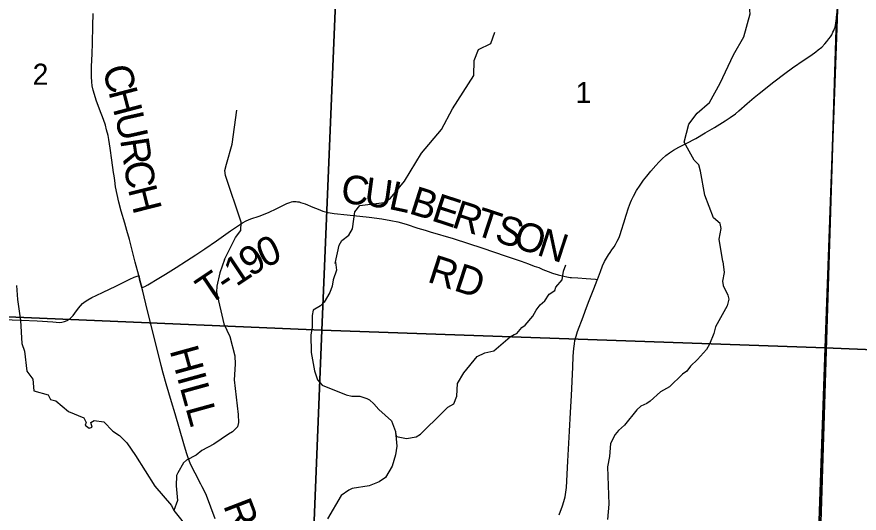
# Model space of a CAD drawing. Extents: x 0 to 34, y 0 to 22.
# Drawn here: x 4.017 to 5.686, y 19.003 to 19.987 of the extents above; entities that cross this region are included whole.
import ezdxf

# ---------------------------------------------------------------- set-up
doc = ezdxf.new("R2010")
doc.units = 0
for name, color, linetype in [('GM_X_County_Road', 7, 'Continuous'), ('GM_X_County_Road_Text', 7, 'Continuous'), ('GM_X_Minor_River', 7, 'Continuous'), ('GM_X_Rail_Line', 7, 'Continuous'), ('GM_X_Section', 7, 'Continuous'), ('GM_X_Section_Text', 7, 'Continuous'), ('GM_X_State_Route', 7, 'Continuous'), ('GM_X_Township_Road', 7, 'Continuous'), ('GM_X_Township_Road_Text', 7, 'Continuous')]:
    doc.layers.add(name, color=color, linetype=linetype)

msp = doc.modelspace()

# ---------------------------------------------------------------- linework, layer by layer
at = {"layer": 'GM_X_County_Road'}
for points in [[(4.2581, 19.4742), (4.2513, 19.5005), (4.2443, 19.5275), (4.2398, 19.5455), (4.2349, 19.5635), (4.2305, 19.5783), (4.2234, 19.602), (4.2186, 19.62), (4.2152, 19.635), (4.2124, 19.6502), (4.2106, 19.6625), (4.2094, 19.6717), (4.2084, 19.6788), (4.205, 19.703), (4.2015, 19.7267), (4.1987, 19.7437), (4.1973, 19.7518), (4.1946, 19.7631), (4.1921, 19.7723), (4.1881, 19.7839), (4.1806, 19.8042), (4.1741, 19.8217), (4.1707, 19.8329), (4.1682, 19.8416), (4.1662, 19.8507), (4.1652, 19.8583), (4.1643, 19.8684), (4.1643, 19.8763), (4.1645, 19.8889), (4.1657, 19.9136), (4.1665, 19.9352), (4.1675, 19.9693), (4.1681, 19.9941)], [(4.2642, 19.4504), (4.2606, 19.4645), (4.2581, 19.4742)], [(4.4099, 18.9919), (4.4008, 19.0151), (4.3944, 19.0326), (4.3909, 19.0412), (4.3842, 19.0551), (4.3815, 19.0607), (4.37, 19.0827), (4.3644, 19.0938), (4.3604, 19.1022), (4.3568, 19.1109), (4.3527, 19.1226), (4.3473, 19.1404), (4.3302, 19.2002), (4.3232, 19.224), (4.3123, 19.2596), (4.3063, 19.2806), (4.3024, 19.2956), (4.29, 19.3469), (4.275, 19.4072), (4.266, 19.4434), (4.2642, 19.4504)]]:
    msp.add_lwpolyline(points, dxfattribs=at)
at = {"layer": 'GM_X_Minor_River'}
for points in [[(5.4162, 19.5024), (5.4088, 19.5463), (5.4128, 19.5672), (5.4109, 19.5774), (5.3972, 19.589), (5.3803, 19.6336), (5.3713, 19.6813), (5.3685, 19.6938), (5.359, 19.7032), (5.3395, 19.7387), (5.3484, 19.7743), (5.3653, 19.7964), (5.3893, 19.8174), (5.4107, 19.8558), (5.4368, 19.9121), (5.4574, 19.9478), (5.4703, 19.9934), (5.4687, 20.0066), (5.4622, 20.0225), (5.4648, 20.0335), (5.4742, 20.0441), (5.4794, 20.0559), (5.4733, 20.068)], [(4.6473, 19.4978), (4.6554, 19.5342), (4.6606, 19.5437), (4.6746, 19.554), (4.6817, 19.5669), (4.6868, 19.6007), (4.6962, 19.6133), (4.7445, 19.6189), (4.7573, 19.6277), (4.7851, 19.6616), (4.8188, 19.7172), (4.8586, 19.7641), (4.8799, 19.8051), (4.9223, 19.8706), (4.9232, 19.9009), (4.9314, 19.9225), (4.9563, 19.9341), (4.9637, 19.9565)], [(4.4279, 19.506), (4.4499, 19.5494), (4.4604, 19.5638), (4.4611, 19.5801), (4.4303, 19.6723), (4.4291, 19.6826), (4.432, 19.6951), (4.4431, 19.7345), (4.4529, 19.8024)], [(4.4279, 19.506), (4.419, 19.4796), (4.413, 19.453), (4.4123, 19.4412), (4.4266, 19.3786), (4.4389, 19.3533), (4.4485, 19.315), (4.4494, 19.2987), (4.4472, 19.2675), (4.4555, 19.1989), (4.456, 19.1829), (4.4541, 19.1742), (4.4443, 19.1643), (4.436, 19.1597), (4.407, 19.1401), (4.3832, 19.1271), (4.3723, 19.1179), (4.3527, 19.108), (4.3467, 19.103), (4.3354, 19.0832), (4.3332, 19.0779), (4.3321, 19.057), (4.3353, 19.0281), (4.3278, 19.0084)], [(4.648, 19.501), (4.6501, 19.4847), (4.6437, 19.466), (4.6415, 19.4535), (4.637, 19.4406), (4.6258, 19.4215), (4.6186, 19.4143), (4.6039, 19.4054), (4.6021, 19.3948), (4.6018, 19.3713), (4.5996, 19.3565), (4.6002, 19.3215), (4.6064, 19.2855), (4.6126, 19.2677), (4.6217, 19.2567), (4.6691, 19.2377), (4.6808, 19.2351), (4.6963, 19.2348), (4.7103, 19.2307), (4.7153, 19.2277), (4.724, 19.2197), (4.7343, 19.2084), (4.759, 19.1865), (4.767, 19.1653), (4.7695, 19.1357), (4.7669, 19.1186), (4.7606, 19.0966), (4.7471, 19.0741), (4.7346, 19.0653), (4.7146, 19.0576), (4.681, 19.0517), (4.6746, 19.049), (4.6591, 19.0379), (4.6325, 18.9919)], [(5.4162, 19.5024), (5.4188, 19.4805), (5.4155, 19.463), (5.4163, 19.4547), (5.4258, 19.4354), (5.4281, 19.4274), (5.4248, 19.4141), (5.4015, 19.3726), (5.3978, 19.3593), (5.3896, 19.3384), (5.3836, 19.3277), (5.3655, 19.3075), (5.3516, 19.2945), (5.3448, 19.2846), (5.3362, 19.2785), (5.3102, 19.2537), (5.3045, 19.2503), (5.2925, 19.2437), (5.2721, 19.2254), (5.265, 19.2204), (5.2536, 19.2154), (5.2457, 19.2082), (5.2213, 19.1777), (5.2089, 19.167), (5.2025, 19.1594), (5.1935, 19.1415), (5.1913, 19.1153), (5.1873, 19.0948), (5.1899, 19.0211), (5.1874, 18.9908)], [(4.7674, 19.1609), (4.769, 19.1551), (4.789, 19.1514), (4.8083, 19.1542), (4.8166, 19.1595), (4.8603, 19.2027), (4.8708, 19.213), (4.8829, 19.2199), (4.8885, 19.2351), (4.8903, 19.2605), (4.9026, 19.2811), (4.929, 19.3135), (4.9444, 19.3208), (4.9618, 19.3247), (4.9946, 19.353), (5.0021, 19.3576), (5.0078, 19.3591), (5.0176, 19.3713), (5.0244, 19.3759), (5.039, 19.3934), (5.0462, 19.4056), (5.0541, 19.4163), (5.0631, 19.4239), (5.0717, 19.4376), (5.0827, 19.4449), (5.0849, 19.451), (5.0973, 19.4655), (5.1003, 19.4826), (5.1047, 19.4955)], [(4.0158, 19.4545), (4.0178, 19.4268), (4.0237, 19.3851), (4.0266, 19.3396), (4.0316, 19.3244), (4.0363, 19.2846), (4.0481, 19.2687), (4.0505, 19.2459), (4.0785, 19.2377), (4.0831, 19.2283), (4.0941, 19.2261), (4.1192, 19.2046), (4.1495, 19.1918), (4.1541, 19.1827), (4.1522, 19.1774), (4.1598, 19.1714), (4.1662, 19.1737), (4.1632, 19.1828), (4.1696, 19.187), (4.1893, 19.1845), (4.2071, 19.1656), (4.22, 19.1573), (4.2345, 19.1426), (4.252, 19.1176), (4.2902, 19.0564), (4.3233, 19.0186), (4.3278, 19.0084)], [(4.3278, 19.0084), (4.3438, 18.9883), (4.3656, 18.9516), (4.3717, 18.9437), (4.3899, 18.9267), (4.4017, 18.9124), (4.4143, 18.8992), (4.4234, 18.8962), (4.4441, 18.9043), (4.4498, 18.905), (4.4653, 18.9025), (4.4816, 18.8931), (4.4976, 18.8765), (4.5082, 18.8697), (4.5291, 18.8535)]]:
    msp.add_lwpolyline(points, dxfattribs=at)
at = {"layer": 'GM_X_Rail_Line'}
for points in [[(6.4497, 20.3378), (5.6557, 20.3708), (5.6553, 20.3577), (5.6546, 20.3418), (5.654, 20.3257), (5.6534, 20.3099), (5.6525, 20.282), (5.6508, 20.2455), (5.6504, 20.2297), (5.6498, 20.2109), (5.648, 20.1614), (5.6476, 20.1497), (5.6463, 20.1174), (5.6454, 20.0833), (5.644, 20.0435), (5.6417, 19.9935), (5.6412, 19.9842), (5.6047, 18.8149), (5.5414, 17.2599)], [(5.5414, 17.2599), (5.6047, 18.8149), (5.6412, 19.9842), (5.6417, 19.9935)]]:
    msp.add_lwpolyline(points, dxfattribs=at)
at = {"layer": 'GM_X_Section'}
for points in [[(4.1631, 20.3865), (4.6595, 20.365), (4.6626, 20.3648), (4.6214, 19.3661), (3.6257, 19.4083), (3.659, 20.4071)], [(5.1633, 20.3473), (5.6549, 20.3275), (5.6189, 19.331), (4.6214, 19.3661), (4.6626, 20.3648)], [(5.6562, 20.3612), (6.6348, 20.3279), (6.5918, 19.2905), (5.6189, 19.331), (5.6549, 20.3275)], [(4.6214, 19.3661), (4.58, 18.3465), (3.5763, 18.3989), (3.6257, 19.4083)], [(5.6189, 19.331), (5.5833, 18.3028), (4.58, 18.3465), (4.6214, 19.3661)], [(6.5918, 19.2905), (6.5595, 18.2824), (5.5833, 18.3028), (5.6189, 19.331)]]:
    msp.add_lwpolyline(points, close=True, dxfattribs=at)
at = {"layer": 'GM_X_State_Route'}
msp.add_lwpolyline([(5.0918, 19.0001), (5.0982, 19.0176), (5.101, 19.0264), (5.1033, 19.0354), (5.1049, 19.0445), (5.1059, 19.0537), (5.1086, 19.1064), (5.1118, 19.1654), (5.114, 19.2026), (5.1158, 19.2367), (5.1186, 19.2924), (5.1195, 19.3142), (5.1205, 19.3297), (5.1217, 19.339), (5.1228, 19.3452), (5.1251, 19.3543), (5.1281, 19.3631), (5.1388, 19.3923), (5.1431, 19.4039), (5.1498, 19.4213), (5.1599, 19.4477), (5.1667, 19.4653), (5.1672, 19.4665), (5.1731, 19.4822), (5.1777, 19.4938), (5.1815, 19.5018), (5.1852, 19.5086), (5.1894, 19.5153), (5.1927, 19.5197), (5.1962, 19.5249), (5.1981, 19.5277), (5.2003, 19.5314), (5.2029, 19.5356), (5.2066, 19.5421), (5.2101, 19.5496), (5.2124, 19.5556), (5.215, 19.5641), (5.2199, 19.5789), (5.2245, 19.5938), (5.229, 19.6088), (5.2308, 19.614), (5.2328, 19.6188), (5.2351, 19.624), (5.239, 19.6315), (5.245, 19.6426), (5.252, 19.6535), (5.2589, 19.6631), (5.2651, 19.6714), (5.273, 19.681), (5.2828, 19.6922), (5.2889, 19.6993), (5.2955, 19.7059), (5.3027, 19.712), (5.3102, 19.7176), (5.318, 19.7228), (5.3287, 19.7291), (5.343, 19.7362), (5.3623, 19.7462), (5.3807, 19.757), (5.3993, 19.7681), (5.4203, 19.7811), (5.4307, 19.7878), (5.4407, 19.795), (5.4479, 19.8008), (5.4641, 19.8151), (5.4781, 19.8274), (5.4876, 19.8353), (5.5169, 19.8582), (5.5391, 19.8751), (5.5542, 19.886), (5.5774, 19.9017), (5.5901, 19.9104), (5.6002, 19.9176), (5.6051, 19.9215), (5.612, 19.9273), (5.6181, 19.9336), (5.6223, 19.9386), (5.6262, 19.9435), (5.6291, 19.9476), (5.6316, 19.9517), (5.634, 19.9565), (5.6358, 19.9603), (5.6372, 19.9639), (5.6383, 19.9668), (5.6392, 19.9699), (5.6401, 19.9745), (5.6414, 19.9836), (5.6419, 19.993)], dxfattribs=at)
at = {"layer": 'GM_X_Township_Road'}
for points in [[(4.2642, 19.4504), (4.2668, 19.4511), (4.2701, 19.4524), (4.2764, 19.456), (4.2977, 19.4688), (4.311, 19.4769), (4.3321, 19.4901), (4.3531, 19.5034), (4.3715, 19.5151), (4.3895, 19.5273), (4.4125, 19.5433), (4.4404, 19.5631), (4.4557, 19.5737), (4.4639, 19.579), (4.4708, 19.5825), (4.4805, 19.5865), (4.4972, 19.5923), (4.5157, 19.5995), (4.532, 19.6069), (4.552, 19.617), (4.5577, 19.6193), (4.5607, 19.6202), (4.5638, 19.6208), (4.567, 19.6209), (4.57, 19.621), (4.573, 19.6207), (4.5761, 19.6201), (4.5791, 19.6192), (4.5879, 19.6162), (4.6035, 19.6098), (4.6138, 19.6056), (4.6232, 19.6019), (4.6336, 19.5995), (4.6457, 19.5973), (4.6713, 19.5943), (4.715, 19.5899), (4.7399, 19.5864), (4.7581, 19.5837), (4.7719, 19.5805), (4.7882, 19.5758), (4.8111, 19.5685), (4.8259, 19.564), (4.8355, 19.561), (4.8812, 19.5474), (4.9401, 19.5287), (4.9846, 19.5136), (5.016, 19.5026), (5.0306, 19.4973), (5.0422, 19.493), (5.0509, 19.4899), (5.0591, 19.4863), (5.0696, 19.4823), (5.078, 19.4791), (5.0893, 19.4759), (5.1008, 19.4729), (5.1068, 19.4714), (5.113, 19.4705), (5.116, 19.4702), (5.1284, 19.4696), (5.1453, 19.4683), (5.1635, 19.4668), (5.1672, 19.4665)], [(3.97, 19.3878), (4.026, 19.386), (4.057, 19.3844), (4.088, 19.3823), (4.0947, 19.3817), (4.1009, 19.3814), (4.1061, 19.3817), (4.1112, 19.3829), (4.1165, 19.3849), (4.1208, 19.3876), (4.125, 19.3914), (4.1285, 19.3952), (4.1317, 19.3995), (4.1387, 19.4096), (4.1426, 19.4144), (4.1465, 19.4185), (4.1518, 19.4227), (4.157, 19.4261), (4.1652, 19.4305), (4.1736, 19.4346), (4.1876, 19.4411), (4.2129, 19.4531), (4.2408, 19.4668), (4.2493, 19.4709), (4.253, 19.4723), (4.2569, 19.4737), (4.2581, 19.4742)], [(4.2581, 19.4742), (4.2606, 19.4645), (4.2642, 19.4504)]]:
    msp.add_lwpolyline(points, dxfattribs=at)

# ---------------------------------------------------------------- texts
at = {"layer": 'GM_X_County_Road_Text'}
for s, height, rotation, p in [('C', 0.0568, 284.7273, (4.1858, 19.8844)), ('H', 0.0568, 284.7219, (4.1977, 19.8393)), ('U', 0.0568, 282.7153, (4.2103, 19.7915)), ('R', 0.0568, 278.6429, (4.2211, 19.7437)), ('C', 0.0568, 278.8058, (4.2281, 19.6974)), ('H', 0.0568, 284.1099, (4.2364, 19.6457)), ('HILL', 0.05682, 285.4589, (4.3191, 19.3261)), ('R', 0.0568, 291.0215, (4.425, 19.0184))]:
    msp.add_text(s, height=height, rotation=rotation, dxfattribs=at).set_placement(p)
at = {"layer": 'GM_X_Section_Text'}
for s, p in [('2', (4.0479, 19.8524)), ('1', (5.1242, 19.8162))]:
    msp.add_text(s, height=0.0419, rotation=0, dxfattribs=at).set_placement(p)
at = {"layer": 'GM_X_Township_Road_Text'}
for s, height, rotation, p in [('C', 0.0568, 352.6973, (4.6569, 19.6192)), ('U', 0.0568, 352.3418, (4.7031, 19.6133)), ('L', 0.0568, 347.7403, (4.7514, 19.6068)), ('B', 0.0568, 342.3957, (4.7916, 19.5982)), ('E', 0.0568, 341.893, (4.836, 19.5841)), ('R', 0.0568, 341.886, (4.8764, 19.5709)), ('T', 0.0568, 341.8849, (4.9207, 19.5564)), ('S', 0.0568, 341.8821, (4.9611, 19.5432)), ('O', 0.0568, 341.883, (4.9975, 19.5313)), ('N', 0.0568, 341.8846, (5.0451, 19.5157)), ('0', 0.0568, 24.0111, (4.5075, 19.4884)), ('9', 0.0568, 33.0276, (4.4803, 19.4705)), ('1', 0.0568, 33.7565, (4.4513, 19.4511)), ('RD', 0.05682, 342.0082, (4.8281, 19.4625)), ('T', 0.0568, 33.9991, (4.3968, 19.4144)), ('-', 0.0568, 33.9585, (4.432, 19.4381))]:
    msp.add_text(s, height=height, rotation=rotation, dxfattribs=at).set_placement(p)

doc.saveas('drawing.dxf')
